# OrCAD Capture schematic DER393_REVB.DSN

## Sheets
1 PAGE3: size C
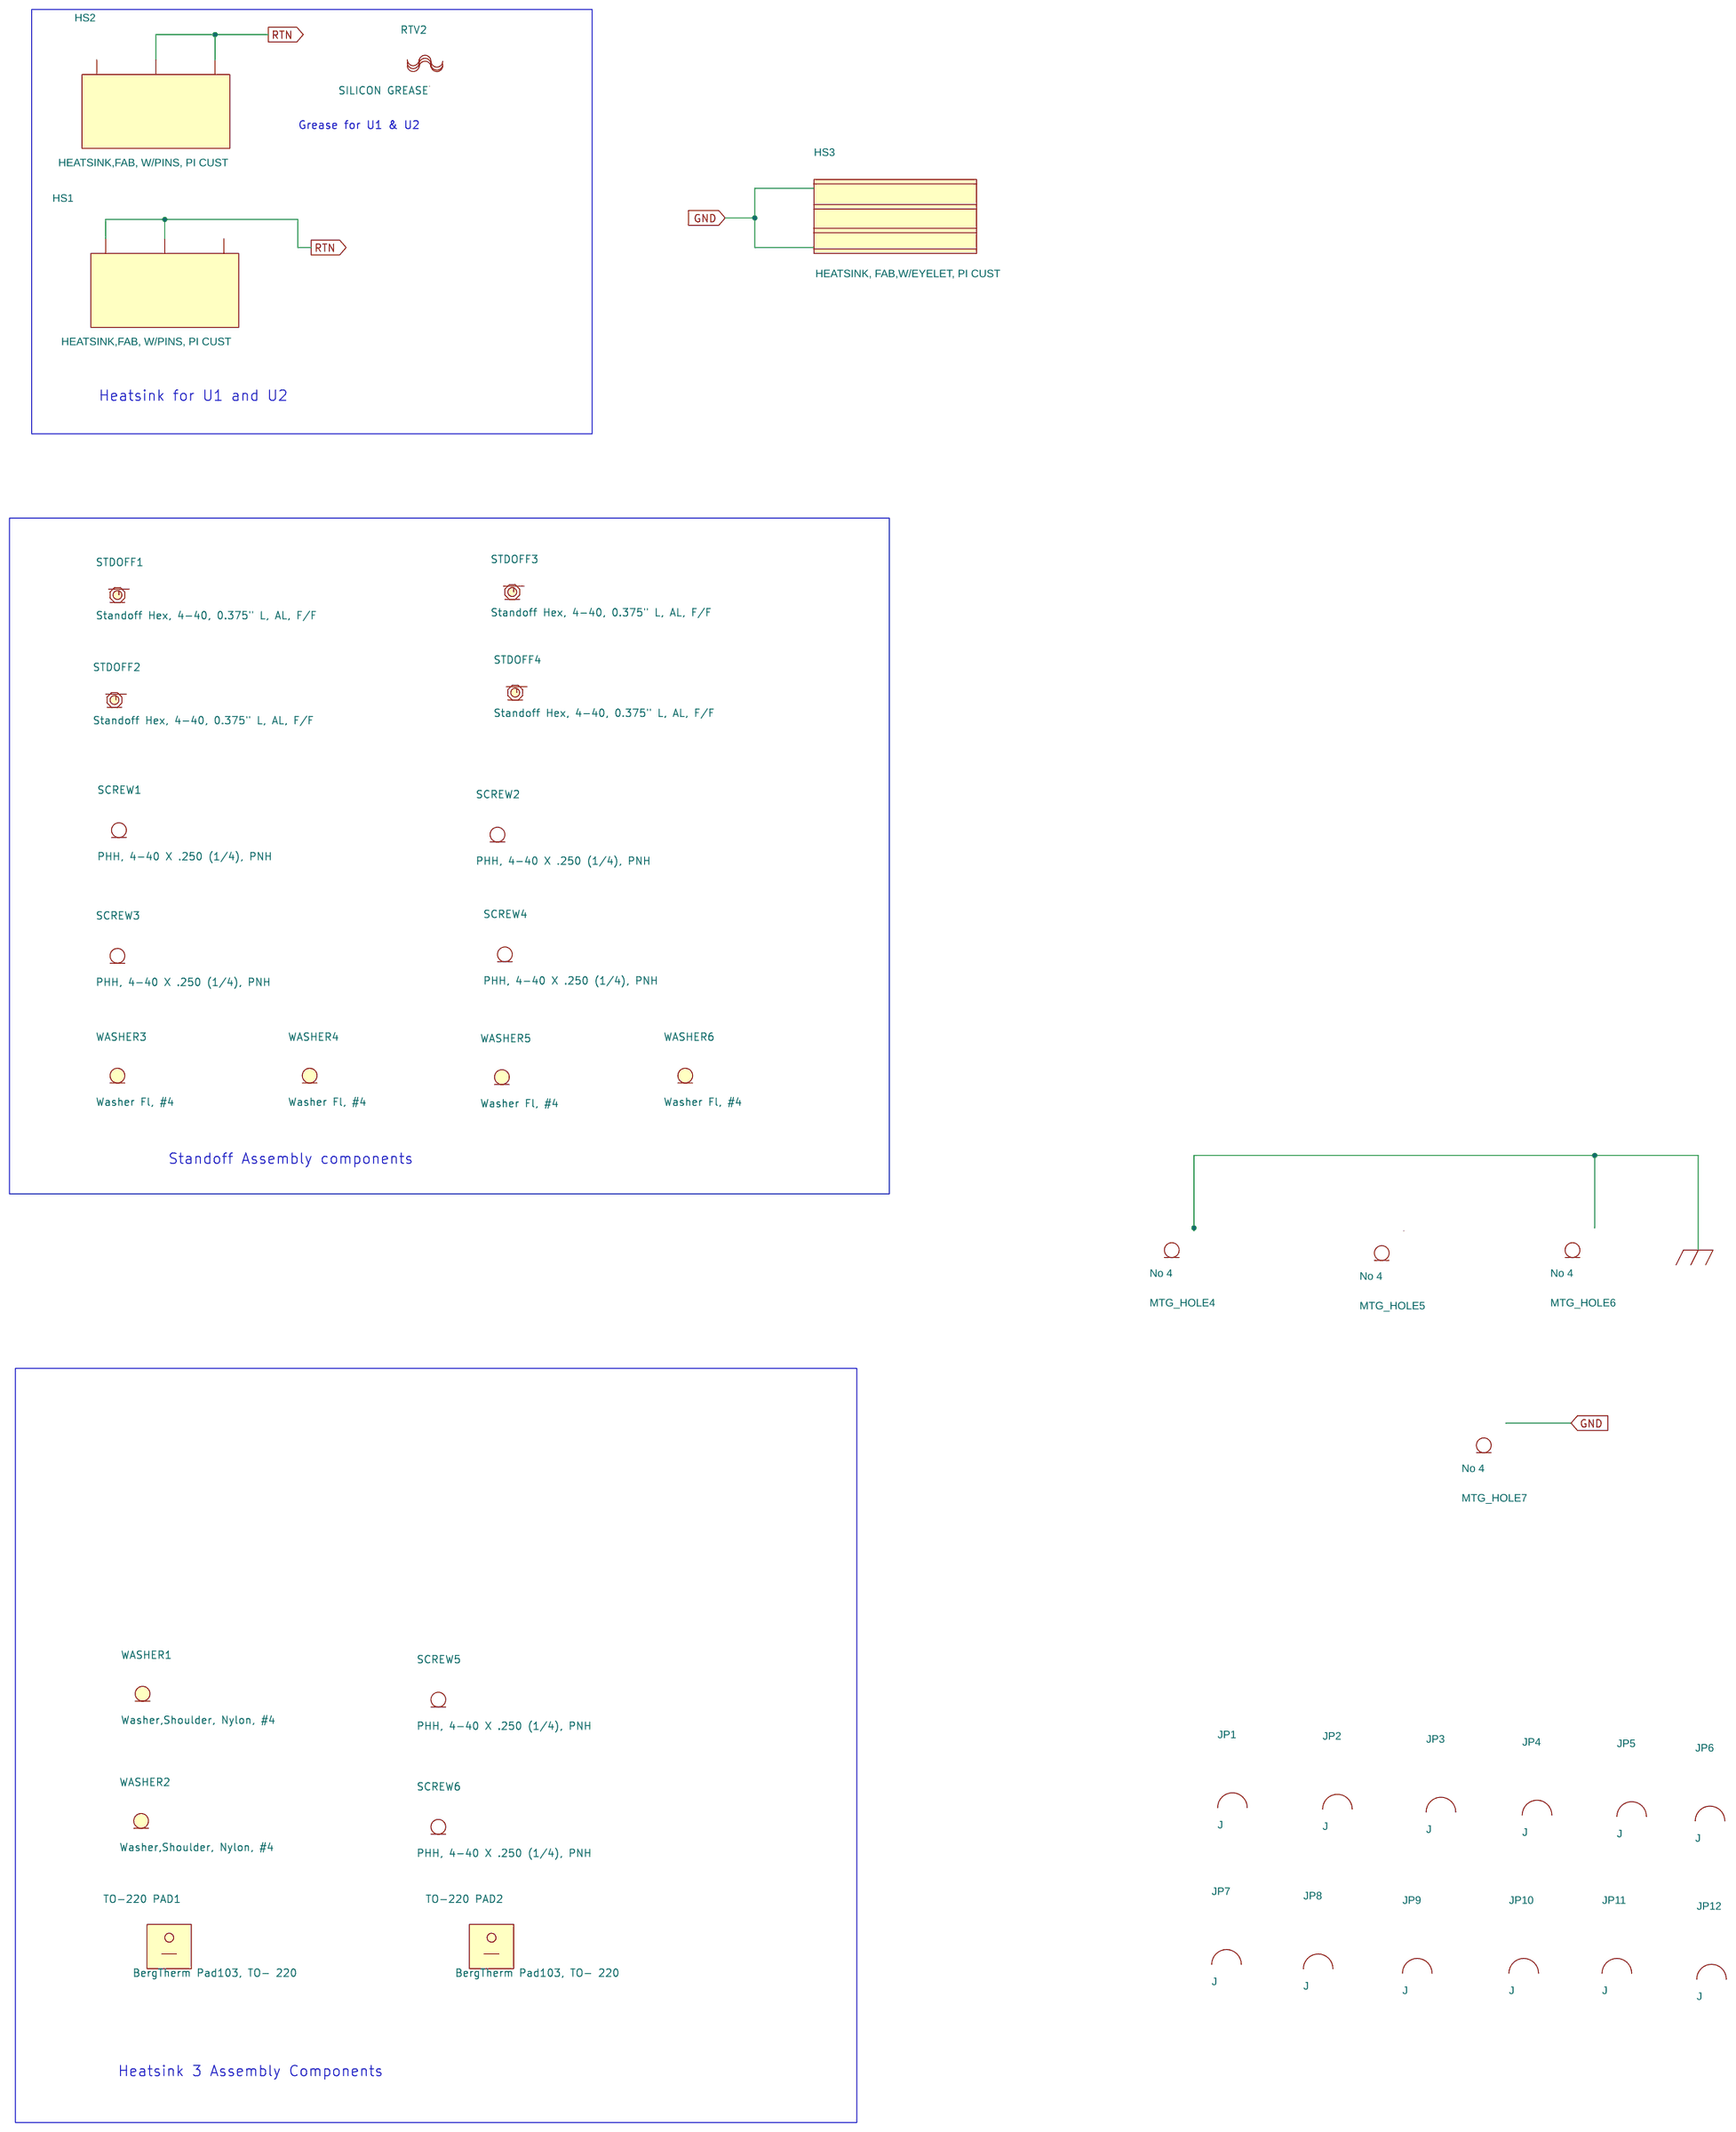
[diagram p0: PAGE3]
2 PAGE2: size C; title: DER393; rev: 2
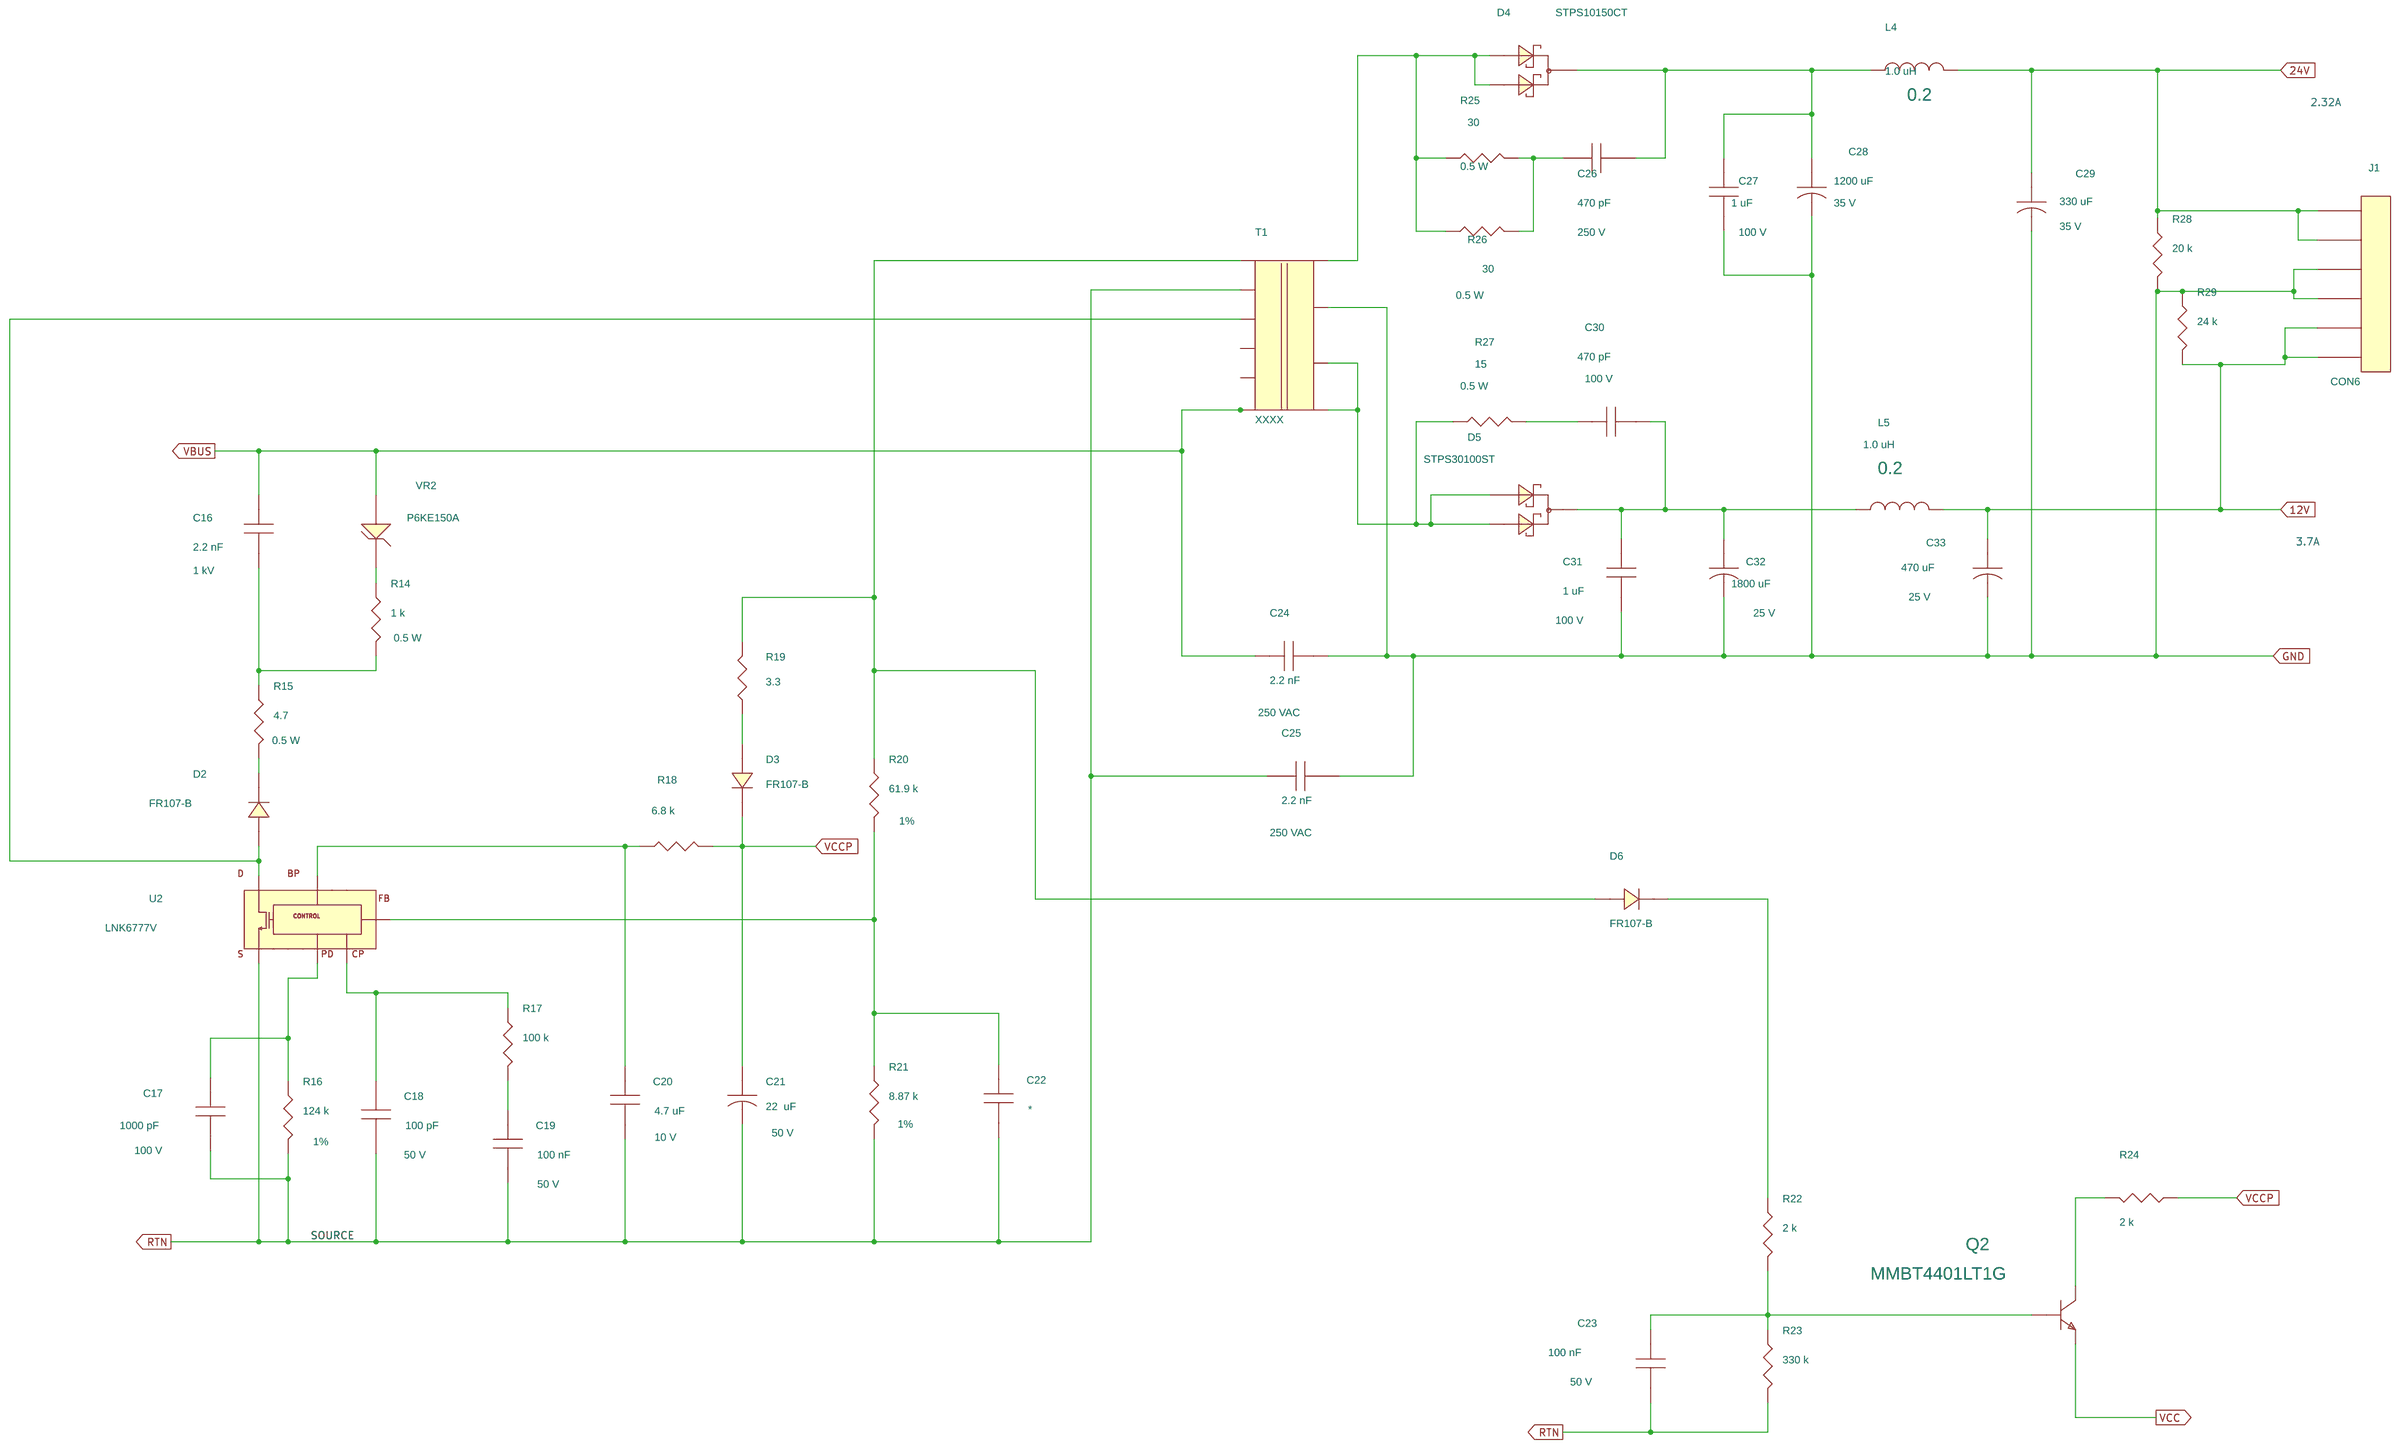
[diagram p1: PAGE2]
3 PAGE1: size C; title: DER393; rev: 1
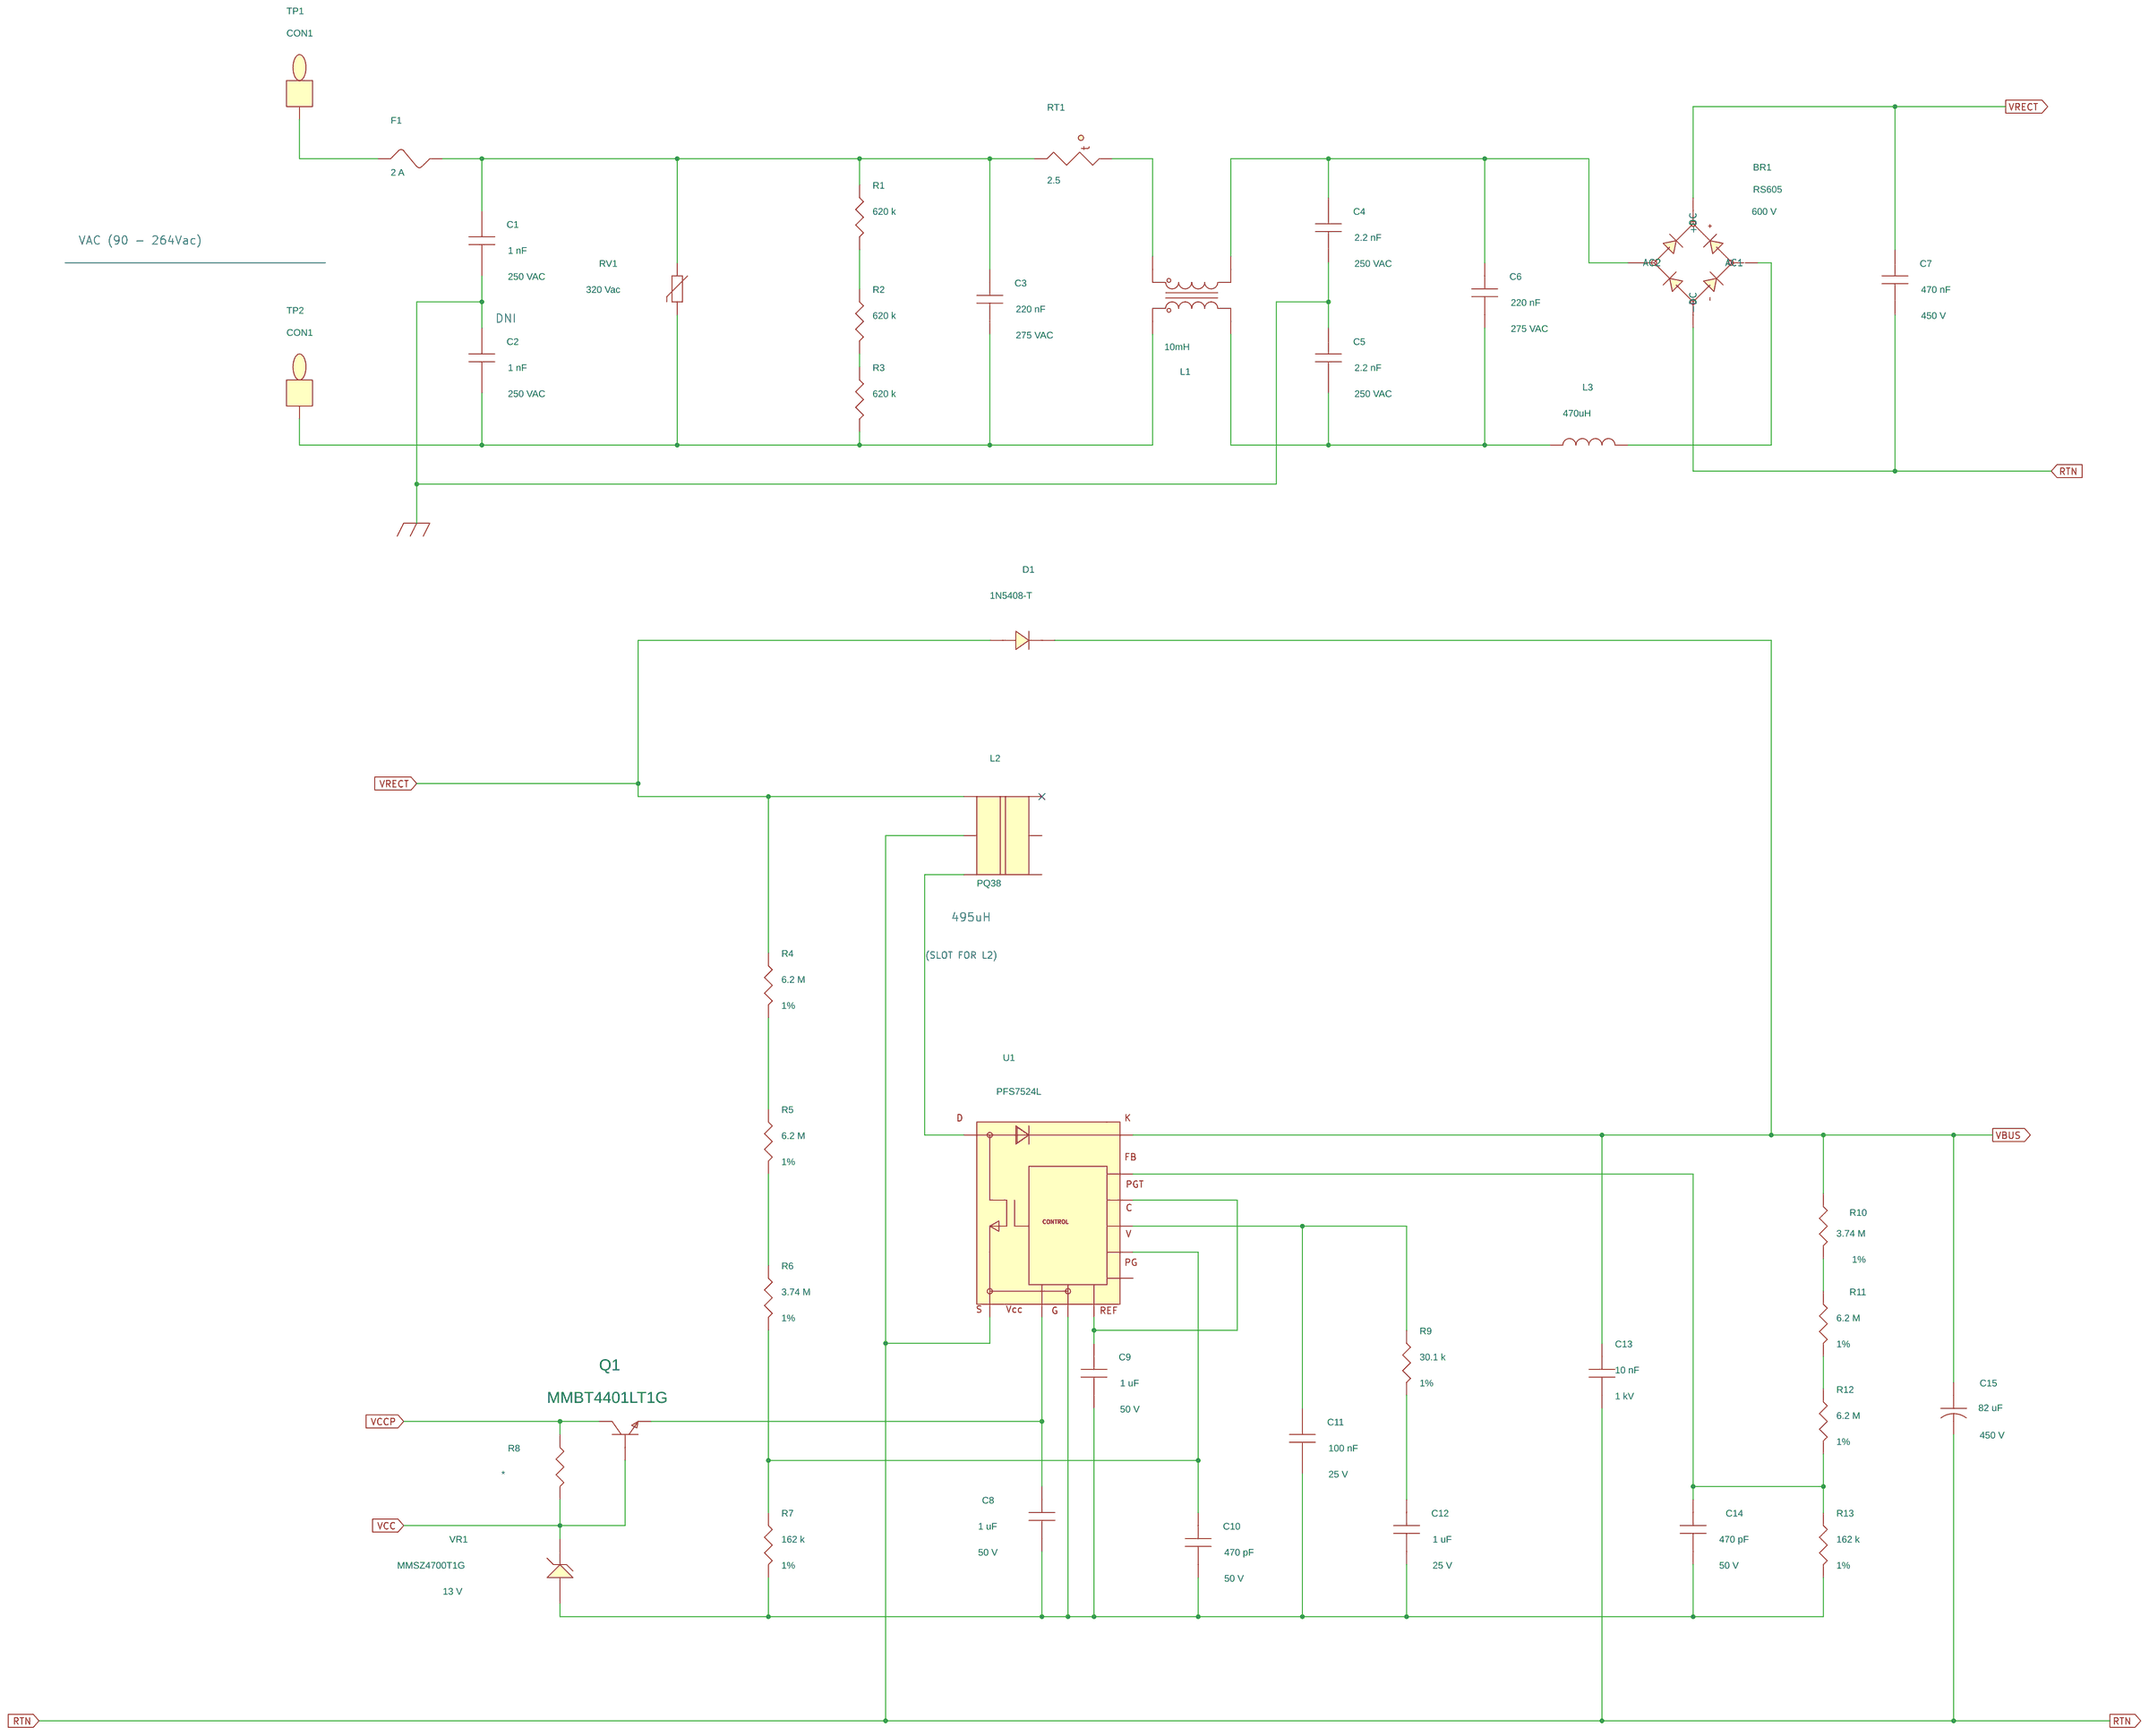
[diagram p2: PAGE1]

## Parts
sheet PAGE1
BR1  RS605  [pi_dax_bridge_rs605_h]
C1  1 nF  [pinpycaprad540x290ls400040]
C2  1 nF  [pinpycaprad540x290ls400040]
C3  220 nF  [pinpcaprad550x395490030horz]
C4  2.2 nF  [pinpycaprad540x290ls400040]
C5  2.2 nF  [pinpycaprad540x290ls400040]
C6  220 nF  [pinpcaprad550x395490030horz]
C7  470 nF  [pi_np_caprad512x345ls394d040]
C8  1 uF  [pismc0805]
C9  1 uF  [pismc0805]
C10  470 pF  [pismc0805]
C11  100 nF  [pismc0805]
C12  1 uF  [pismc0805]
C13  10 nF  [pi_np_cap250x200ls170d030]
C14  470 pF  [pismc0805]
C15  82 uF  [pi_pcap_d500ls200_040_2000h]
D1  1N5408-T  [pidax800x225060do15do201ad]
F1  2 A  [pi_tr5_submin_fuse]
L1  10mH  [pi_ind_4p_690x512ls300x200d055]
L2  PQ38  [pi_bobbin_pq38_6p]
L3  470uH  [pi_2p_700x400d055_horiz]
Q1  MMBT4401LT1G  [pismsot23132]
R1  620 k  [pismr1206]
R2  620 k  [pismr1206]
R3  620 k  [pismr1206]
R4  6.2 M  [pismr1206]
R5  6.2 M  [pismr1206]
R6  3.74 M  [pi14wresd100ls500d030]
R7  162 k  [pismr0805]
R8  *  [pismr1206]
R9  30.1 k  [pismr1206]
R10  3.74 M  [pi14wvresd100ls100d030]
R11  6.2 M  [pismr1206]
R12  6.2 M  [pismr1206]
R13  162 k  [pismr0805]
RT1  2.5  [pi_rad150x300ls200d030]
RV1  320 Vac  [pi_rad450x550ls300d040_h]
TP1  CON1  [pitpkeystone125x125]
TP2  CON1  [pitpkeystone125x125]
U1  PFS7524L  [piiclbendesiplg]
VR1  MMSZ4700T1G  [pi_sm_sod-123_12]
sheet PAGE2
C16  2.2 nF  [pinpcaprad350x100200030]
C17  1000 pF  [pismc0603]
C18  100 pF  [pismc0603]
C19  100 nF  [pismc0603]
C20  4.7 uF  [pismc0805]
C21  22  uF  [pipolcapclyd200ls80030]
C22  *  [pismc0805]
C23  100 nF  [pismc0805]
C24  2.2 nF  [pinpycaprad540x290ls400040]
C25  2.2 nF  [pinpycaprad540x290ls400040]
C26  470 pF  [pismc0805]
C27  1 uF  [pismc1206]
C28  1200 uF  [pipolcapclyd500ls2000401200lh]
C29  330 uF  [pipolcapclyd395x630ls200030h]
C30  470 pF  [pismc0805]
C31  1 uF  [pismc1206]
C32  1800 uF  [pipolcapclyd500ls2000401200lh]
C33  470 uF  [pipolcapclyd395x630ls200030h]
D2  FR107-B  [pidv200x110x040do41]
D3  FR107-B  [pidv200x110x040do41]
D4  STPS10150CT  [pidvto2203vf1h]
D5  STPS30100ST  [pidvto2203vf1h]
D6  FR107-B  [pidv200x110x040do41]
J1  CON6  [pi_hdr_6pin_lock]
L4  1.0 uH  [pi_choke_tok441ls197d043]
L5  1.0 uH  [pi_choke_tok441ls197d043]
Q2  MMBT4401LT1G  [pismsot23132]
R14  1 k  [pi12wresd180ls675d040]
R15  4.7  [pi12wresd180ls675d040]
R16  124 k  [pismr0603]
R17  100 k  [pismr0603]
R18  6.8 k  [pismr0805]
R19  3.3  [pismr1206]
R20  61.9 k  [pi14wresd100ls400d030]
R21  8.87 k  [pismr0603]
R22  2 k  [pismr0805]
R23  330 k  [pismr0805]
R24  2 k  [pismr0603]
R25  30  [pi12wvresd180ls150d040]
R26  30  [pi12wvresd180ls150d040]
R27  15  [pi12wvresd180ls150d040]
R28  20 k  [pismr1206]
R29  24 k  [pismr1206]
T1  XXXX  [pi_bobbin_pq3812_10p_1800ls]
U2  LNK6777V  [pi_ic_edip_11-12p]
VR2  P6KE150A  [pidv200x140x050do15do204ac]
sheet PAGE3
HS1  HEATSINK,FAB, W/PINS, PI CUST  [pi_hs_PFS3_LNKHP110W]
HS2  HEATSINK,FAB, W/PINS, PI CUST  [pi_hs_PFS3_LNKHP110W]
HS3  HEATSINK, FAB,W/EYELET, PI CUST  [pi_hs_diodes_sec_der393]
JP1  J  [pi_jumper500]
JP2  J  [pi_jumper600]
JP3  J  [pi_jumper1200]
JP4  J  [pi_jumper300]
JP5  J  [pi_jumper400]
JP6  J  [pi_jumper1700]
JP7  J  [pi_jumper1600]
JP8  J  [pi_jumper300]
JP9  J  [pi_jumper300]
JP10  J  [pi_jumper700]
JP11  J  [pi_jumper900]
JP12  J  [pi_jumper1200-18awg-sld]
MTG_HOLE4  No 4  [pimtghole4]
MTG_HOLE5  No 4  [pimtghole4]
MTG_HOLE6  No 4  [pimtghole4]
MTG_HOLE7  No 4  [pimtghole4]
RTV2  SILICON GREASE
SCREW1  PHH, 4-40 X .250 (1/4), PNH
SCREW2  PHH, 4-40 X .250 (1/4), PNH
SCREW3  PHH, 4-40 X .250 (1/4), PNH
SCREW4  PHH, 4-40 X .250 (1/4), PNH
SCREW5  PHH, 4-40 X .250 (1/4), PNH
SCREW6  PHH, 4-40 X .250 (1/4), PNH
STDOFF1  Standoff Hex, 4-40, 0.375" L, AL, F/F
STDOFF2  Standoff Hex, 4-40, 0.375" L, AL, F/F
STDOFF3  Standoff Hex, 4-40, 0.375" L, AL, F/F
STDOFF4  Standoff Hex, 4-40, 0.375" L, AL, F/F
TO-220 PAD1  BergTherm Pad103, TO- 220
TO-220 PAD2  BergTherm Pad103, TO- 220
WASHER1  Washer,Shoulder, Nylon, #4
WASHER2  Washer,Shoulder, Nylon, #4
WASHER3  Washer Fl, #4
WASHER4  Washer Fl, #4
WASHER5  Washer Fl, #4
WASHER6  Washer Fl, #4

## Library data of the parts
BR1 = DIODE_BRIDGE_1234: Disp_Voltage: 600 V; FPLIST: pi_dax_bridge_rs605,pi_dax_bridge_rs605_h; Part Number: 15-00696-00
C1 C2 = CAP_NP: ALT_SYMBOLS: pinpycaprad540x290ls400040h; Disp_Voltage: 250 VAC; FPLIST: pinpycaprad540x290ls400040,pinpycaprad540x290ls400040h; Part Number: 20-00375-00; Voltage: 250 VAC
C3 C6 = CAP_NP: Disp_Voltage: 275 VAC; FPLIST: pi_np_xcap_rad550x330ls493d040,pinpcaprad550x395490030horz; Part Number: 20-00777-00; Voltage: 275 VAC
C4 C5 C24 C25 = CAP_NP: ALT_SYMBOLS: pinpycaprad540x290ls400040h; Disp_Voltage: 250 VAC; FPLIST: pinpycaprad540x290ls400040,pinpycaprad540x290ls400040h; Part Number: 20-00376-00; Voltage: 250 VAC
C7 = CAP_NP: Disp_Voltage: 450 V; Part Number: 20-08713-00; Voltage: 450 V
C8 C9 = CAP_NP: Disp_Voltage: 50 V; Part Number: 20-01022-00; Voltage: 50 V
C10 C14 = CAP_NP: Disp_Voltage: 50 V; Part Number: 20-00205-00; Voltage: 50 V
C11 = CAP_NP: Disp_Voltage: 25 V; Part Number: 20-08599-00; Voltage: 25 V
C12 = CAP_NP: Disp_Voltage: 25 V; Part Number: 20-00923-00; Voltage: 25 V
C13 = CAP_NP: Disp_Voltage: 1 kV; Part Number: 20-00906-00; Tol: 20; Voltage: 1 kV
C15 = CAP_POL: Disp_Voltage: 450 V; FPLIST: pipolcapclyd500ls200040,pi_pcap_d500ls200_040_2000h; Part Number: 20-00991-00; Voltage: 450 V
D1 = DIODE: ALT_SYMBOLS: pidax800x225060do15do201ad,pidv300x200x060do14wbead; FPLIST: pidv300x200x060do15d0201ad,pidax800x225060do15do201ad,pidv300x200x060do14wbead; Part Number: 15-00719-00
F1 = FUSE: Part Number: 40-00002-00
L1 = INDUCTOR_4P_revD: ALT_SYMBOLS: pi_4p_700x400d055_horiz; FPLIST: pi_ind_4p_690x512ls300x200d055,pi_4p_700x400d055_horiz; Part Number: 30-00399-00
L2 = BPQ38_6P_GENERIC: Part Number: 25-00959-00
L3 = INDUCTOR: FPLIST: pi_toroid_2p_350x860_ls330_d038,pi_2p_700x400d055_horiz; Part Number: 32-00224-00
Q1 Q2 = NPN_BEC: Part Number: 55-00059-00
R1-R3 = R: Part Number: 05-01419-00
R4 R5 R11 R12 = R: Disp_Tol: 1%; Part Number: 05-05567-00
R6 R10 = R: ALT_SYMBOLS: pi14wvresd100ls200d030,pi14wresd100ls400d030,pi14wresd100ls500d030; Disp_Tol: 1%; FPLIST: pi14wvresd100ls100d030,pi14wvresd100ls200d030,pi14wresd100ls400d030,pi14wresd100ls500d030; Part Number: 05-05566-00
R7 R13 = R: Disp_Tol: 1%; Part Number: 05-00800-00
R8 = R: Part Number: 05-01376-00
R9 = R: Disp_Tol: 1%; Part Number: 05-00335-00
RT1 = THERMISTOR: FPLIST: pi_rad150x300ls200d030,pirad400x300ls200040_h; Part Number: 90-00040-00
RV1 = VARISTOR: FPLIST: pidisc500x225ls335x140040,pi_rad450x550ls300d040_h; Part Number: 85-00018-00
TP1 = TESTPOINT: Part Number: 35-00042-00
TP2 = TESTPOINT: Part Number: 35-00044-00
U1 = DEV_HIPERPFS-3-eSIP-16C: FPLIST: piiclbendesiplg,piiclbendesiplg_socket; Part Number: 10-00686-00
VR1 = DIODE_ZENER: Disp_Voltage: 13 V; Part Number: 15-01046-00
C16 = CAP_NP: Disp_Voltage: 1 kV; Part Number: 20-00357-00; Tol: 10; Voltage: 1 kV
C17 = CAP_NP: Disp_Voltage: 100 V; Part Number: 20-00712-00; Voltage: 100 V
C18 = CAP_NP: Disp_Voltage: 50 V; Part Number: 20-01025-00; Voltage: 50 V
C19 = CAP_NP: Disp_Voltage: 50 V; Part Number: 20-00936-00; Voltage: 50 V
C20 = CAP_NP: Disp_Voltage: 10 V; Part Number: 20-00612-00; Voltage: 10 V
C21 = CAP_POL: ALT_SYMBOLS: pipolcapclyd200ls80030h; Disp_Voltage: 50 V; FPLIST: pipolcapclyd200ls80030,pipolcapclyd200ls80030h; Part Number: 20-00950-00; Voltage: 50 V
C22 = CAP_NP: Disp_Voltage: 50 V; Part Number: 20-08596-00; Voltage: 50 V
C23 = CAP_NP: Disp_Voltage: 50 V; Part Number: 20-00904-00; Voltage: 50 V
C26 = CAP_NP: Disp_Voltage: 250 V; Part Number: 20-01001-00; Tol: 10; Voltage: 250 V
C27 C31 = CAP_NP: Disp_Voltage: 100 V; Part Number: 20-00717-00; Voltage: 100 V
C28 = CAP_POL: Disp_Voltage: 35 V; FPLIST: pipolcapclyd500ls200040,pipolcapclyd500ls2000401200lh; PCB Editor PCBFP: pipolcapclyd500ls200040; Part Number: 20-00128-00; Tol: 20; Voltage: 35 V
C29 = CAP_POL: Disp_Voltage: 35 V; FPLIST: pipolcapcyld400ls200040,pipolcapclyd395x630ls200030h; PCB Editor PCBFP: pipolcapcyld400ls200040; Part Number: 20-00047-00; Tol: 20; Voltage: 35 V
C30 = CAP_NP: Disp_Voltage: 100 V; Part Number: 20-00905-00; Tol: 10
C32 = CAP_POL: Disp_Voltage: 25 V; FPLIST: pipolcapclyd500ls200040,pipolcapclyd500ls2000401200lh; Part Number: 20-00037-00; Tol: 20; Voltage: 25 V
C33 = CAP_POL: Disp_Voltage: 25 V; FPLIST: pipolcapcyld400ls200040,pipolcapclyd395x630ls200030h; PCB Editor PCBFP: pipolcapcyld400ls200040; Part Number: 20-00032-00; Tol: 20; Voltage: 25 V
D2 D3 D6 = DIODE: ALT_SYMBOLS: pidax475x125040do41,pidv200x110x040do41wbead,pidax390x125040do41; FPLIST: pidv200x110x040do41,pidax475x125040do41,pidv200x110x040do41wbead,pidax390x125040do41; Part Number: 15-00956-00
D4 = DS_DUAL_CK_AKA: ALT_SYMBOLS: pidvto2203,pidvto2203vf1,pidvto2203vf1h; FPLIST: PITO220ABVF1,pidvto2203,pidvto2203vf1,pidvto2203vf1h; Part Number: 15-00668-00
D5 = DS_DUAL_CK_A_AC: ALT_SYMBOLS: pidvto2203vf1; FPLIST: pidvto2203,pidvto2203vf1,pidvto2203vf1h; Part Number: 15-00888-00
J1 = CON6: Part Number: 35-00194-00
L4 L5 = INDUCTOR: Part Number: 30-00265-00; Tol: 0.2
R14 = R: ALT_SYMBOLS: pi12wvresd180ls200d040,pi12wvresd180ls250d040,pi12wresd180ls675d040; Disp_Power: 0.5 W; FPLIST: pi12wvresd180ls150d040,pi12wvresd180ls200d040,pi12wvresd180ls250d040,pi12wresd180ls675d040; PCB Editor PCBFP: pi1wresd200ls725d040,pi1wvresd200ls300d040; Part Number: 05-02675-00; Tol: 5%
R15 = R: ALT_SYMBOLS: pi12wvresd180ls200d040,pi12wvresd180ls250d040,pi12wresd180ls675d040; Disp_Power: 0.5 W; FPLIST: pi12wvresd180ls150d040,pi12wvresd180ls200d040,pi12wvresd180ls250d040,pi12wresd180ls675d040; Part Number: 05-02619-00
R16 = R: Disp_Tol: 1%; Part Number: 05-01183-00
R17 = R: Part Number: 05-01736-00
R18 = R: Part Number: 05-01539-00
R19 = R: Part Number: 05-01292-00
R20 = R: ALT_SYMBOLS: pi14wvresd100ls200d030,pi14wresd100ls400d030,pi14wresd100ls500d030; Disp_Tol: 1%; FPLIST: pi14wvresd100ls100d030,pi14wvresd100ls200d030,pi14wresd100ls400d030,pi14wresd100ls500d030; Part Number: 05-02148-00
R21 = R: Disp_Tol: 1%; Part Number: 05-01169-00
R22 = R: Part Number: 05-01526-00
R23 = R: Part Number: 05-01579-00
R24 = R: Part Number: 05-01695-00
R25 R26 = R: ALT_SYMBOLS: pi12wvresd180ls200d040,pi12wvresd180ls250d040,pi12wresd180ls675d040; Disp_Power: 0.5 W; FPLIST: pi12wvresd180ls150d040,pi12wvresd180ls200d040,pi12wvresd180ls250d040,pi12wresd180ls675d040; PCB Editor PCBFP: pismr1206; Part Number: 05-02638-00; Tol: 5%
R27 = R: ALT_SYMBOLS: pi12wvresd180ls200d040,pi12wvresd180ls250d040,pi12wresd180ls675d040; Disp_Power: 0.5 W; FPLIST: pi12wvresd180ls150d040,pi12wvresd180ls200d040,pi12wvresd180ls250d040,pi12wresd180ls675d040; PCB Editor PCBFP: pismr1206; Part Number: 05-02631-00; Tol: 5%
R28 = R: Part Number: 05-01383-00
R29 = R: Part Number: 05-01385-00
T1 = BPQ3812_10P_GENERIC: Part Number: 25-01035-00
U2 = DEV_LNKHP_eDIP_eSOP: Part Number: 10-00432-00
VR2 = DIODE_ZENER: ALT_SYMBOLS: pidax550x140050do15do204ac; FPLIST: pidv200x140x050do15do204ac,pidax550x140050do15do204ac; Part Number: 15-00619-00
HS1 = HS-PI_CUSTOM_0: Part Number: 61-00158-01
HS2 = HS-PI_CUSTOM_1: Part Number: 61-00158-01
HS3 = HS-PI_CUSTOM2: Part Number: 61-00147-01
JP1 = JUMPER_1: Part Number: 65-00004-00
JP2 = JUMPER_1: Part Number: 65-00123-00
JP3 = JUMPER_1: Part Number: 65-00129-00
JP4 JP8 JP9 = JUMPER_1: Part Number: 65-00120-00
JP5 = JUMPER_1: Part Number: 65-00121-00
JP6 = JUMPER_1: Part Number: 65-00134-00
JP7 = JUMPER_1: Part Number: 65-00133-00
JP10 = JUMPER_1: Part Number: 65-00124-00
JP11 = JUMPER_1: Part Number: 65-00126-00
JP12 = JUMPER_1: Part Number: 65-00090-00
MTG_HOLE4-MTG_HOLE7 = MTG_HOLE_6-32: Part Number: 66-00019-00
RTV2 = RTV: Part Number: 66-00084-00
SCREW1-SCREW6 = SCR_4-40: Part Number: 75-00001-00
STDOFF1-STDOFF4 = STDOFF_HEX_4-40: Part Number: 76-00023-00
TO-220 PAD1 TO-220 PAD2 = Berguist_TO-220_Pad: Part Number: 66-00096-00
WASHER1 WASHER2 = WASH_FLAT_4: Part Number: 75-00071-00
WASHER3-WASHER6 = WASH_FLAT_4: Part Number: 75-00032-00

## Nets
12V: C33.1 J1.1 J1.2 L5.2 R29.2
24V: C29.1 J1.5 J1.6 L4.2 R28.1
GND: C24.2 C25.2 C27.2 C28.2 C29.2 C31.2 C32.2 C33.2 HS3.1 HS3.2 J1.3 J1.4 MTG_HOLE7.1 R28.2 R29.1 T1.9
GND_EARTH: C1.2 C2.1 C4.2 C5.1 MTG_HOLE4.1 MTG_HOLE6.1
VBUS: C13.1 C15.1 C16.1 C24.1 D1.1 R10.1 T1.6 U1.16(K) VR2.2
VCC: Q1.1(BASE) Q2.2(EMITTER) R8.2 VR1.1
VCCP: C21.1 D3.1 Q1.3(COLLECTOR) R8.1 R18.2 R24.1
NC: U1.14(NC)
SOURCE: BR1.4(-DC) C7.2 C13.2 C15.2 C17.2 C18.2 C19.2 C20.2 C21.2 C22.2 C23.2 C25.1 HS1.1 HS1.2 HS2.2 HS2.3 L2.2 R16.2 R21.2 R23.2 T1.2 U1.10(S1) U1.11(SOURCE) U2.7(S7) U2.8(SOURCE) U2.9(SOURCE) U2.10(SOURCE) U2.11(SOURCE) U2.12(SOURCE)
VRECT: BR1.1(+DC) C7.1 D1.2 L2.1 R4.1
N03629: BR1.2(AC1) L3.2
N548426: R1.2 R2.1
N561104: C2.2 C3.2 L1.1 R3.2 RV1.2 TP2.1
N565893: F1.1 TP1.1
N762808: C1.1 C3.1 F1.2 R1.1 RT1.1 RV1.1
N766734: BR1.3(AC2) C4.1 C6.1 L1.3
N1756866: C8.2 C9.2 C10.2 C11.2 C12.2 C14.2 R7.2 R13.2 U1.4(G) VR1.2
N1927297: C12.1 R9.2
N1947560: C5.2 C6.2 L1.2 L3.1
N2112567: L2.3 U1.13(D)
N2121451: C10.1 R6.2 R7.1 U1.5(V)
N2121492: C9.1 U1.3(REF) U1.9(PGT)
N2121508: C8.1 Q1.2(EMITTER) U1.1(Vcc)
N2122246: C14.1 R12.2 R13.1 U1.7(FB)
N2122529: C11.1 R9.1 U1.6(C)
N2126475: R4.2 R5.1
N2126479: R5.2 R6.1
N2213244: L1.4 RT1.2
N2334561: C16.2 R14.2 R15.1
N2334704: D2.2 T1.3 U2.6(D)
N2334708: D2.1 R15.2
N2334716: C17.1 R16.1 U2.1(PD)
N2334802: C19.1 R17.2
N2334806: C18.1 R17.1 U2.3(CP)
N2334875: C22.1 R20.2 R21.1 U2.2(FB)
N2334923: C20.1 R18.1 U2.4(BP)
N2335058: R14.1 VR2.1
N2335116: D6.2 R19.2 R20.1 T1.1
N2335134: D3.2 R19.1
N2335668: D4.1(A1) D4.3(A2) R25.1 R26.2 T1.10
N2335702: D5.1(A1) D5.3(A2) R27.1 T1.7 T1.8
N2335990: C30.1 R27.2
N2336003: C30.2 C31.1 C32.1 D5.2(K) L5.1
N2336055: C26.1 R25.2 R26.1
N2336076: C26.2 C27.1 C28.1 D4.2(CATHODE) L4.1
N4685146: D6.1 R22.1
N4685154: C23.1 Q2.1(BASE) R22.2 R23.1
N4699564: Q2.3(COLLECTOR) R24.2
N4704043: R2.2 R3.1
N4742949: R10.2 R11.1
N4743334: R11.2 R12.1

Not connected (* = marked no-connect by the designer): HS1 3; HS2 1; JP1 1 2; JP2 1 2; JP3 1 2; JP4 1 2; JP5 1 2; JP6 1 2; JP7 1 2; JP8 1 2; JP9 1 2; JP10 1 2; JP11 1 2; JP12 1 2; L2 4 5 6*; MTG_HOLE5 1; T1 4 5; U1 8(PG)

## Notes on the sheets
sheet 1
- Grease for U1 & U2
- Heatsink for U1 and U2
- Standoff Assembly components
- Heatsink 3 Assembly Components
sheet 2
- 2.32A
- 3.7A
sheet 3
- VAC (90 - 264Vac)
- DNI
- 495uH
- (SLOT FOR L2)
